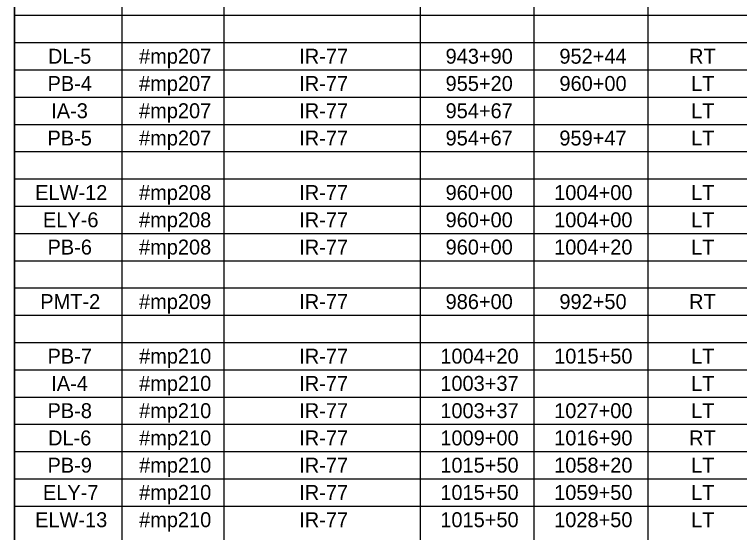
# Model space of a CAD drawing. Extents: x 91011267 to 91022583, y 37007614 to 37014266.
# Drawn here: x 91011277.4 to 91011642.6, y 37008138.9 to 37008399.9 of the extents above; entities that cross this region are included whole.
import ezdxf

# ---------------------------------------------------------------- set-up
doc = ezdxf.new("R2010")
doc.units = 0
doc.layers.add('SC_Scratch2', color=7, linetype='Continuous')
doc.layers.add('SH_Data', color=7, linetype='Continuous')

msp = doc.modelspace()

# ---------------------------------------------------------------- linework, layer by layer
at = {"layer": 'SC_Scratch2'}
msp.add_lwpolyline([(91011277.35, 37008663.81), (91012802.35, 37008663.81), (91012802.35, 37007613.81), (91011277.35, 37007613.81)], close=True, dxfattribs=at)
at = {"layer": 'SH_Data'}
for p, q in [((91011277.35, 37008481.94), (91011277.35, 37008372.04)), ((91011331.39, 37008481.94), (91011331.39, 37008372.04)), ((91011382.8, 37008481.94), (91011382.8, 37008372.04)), ((91011481.65, 37008481.94), (91011481.65, 37008372.04)), ((91011538.99, 37008481.94), (91011538.99, 37008372.04)), ((91011596.32, 37008481.94), (91011596.32, 37008372.04)), ((91011277.35, 37008399.51), (91011596.32, 37008399.51)), ((91011596.32, 37008399.51), (91011650.36, 37008399.51)), ((91011277.35, 37008385.77), (91011596.32, 37008385.77)), ((91011596.32, 37008385.77), (91011650.36, 37008385.77)), ((91011277.35, 37008372.04), (91011596.32, 37008372.04)), ((91011277.35, 37008372.04), (91011277.35, 37008358.3)), ((91011331.39, 37008372.04), (91011331.39, 37008358.3)), ((91011382.8, 37008372.04), (91011382.8, 37008358.3)), ((91011481.65, 37008372.04), (91011481.65, 37008358.3)), ((91011538.99, 37008372.04), (91011538.99, 37008358.3)), ((91011596.32, 37008372.04), (91011650.36, 37008372.04)), ((91011596.32, 37008372.04), (91011596.32, 37008358.3)), ((91011277.35, 37008358.3), (91011596.32, 37008358.3)), ((91011277.35, 37008358.3), (91011277.35, 37008330.82)), ((91011331.39, 37008358.3), (91011331.39, 37008330.82)), ((91011382.8, 37008358.3), (91011382.8, 37008330.82)), ((91011481.65, 37008358.3), (91011481.65, 37008330.82)), ((91011538.99, 37008358.3), (91011538.99, 37008330.82)), ((91011596.32, 37008358.3), (91011650.36, 37008358.3)), ((91011596.32, 37008358.3), (91011596.32, 37008330.82)), ((91011277.35, 37008344.56), (91011596.32, 37008344.56)), ((91011596.32, 37008344.56), (91011650.36, 37008344.56)), ((91011277.35, 37008330.82), (91011596.32, 37008330.82)), ((91011277.35, 37008330.82), (91011277.35, 37008317.08)), ((91011331.39, 37008330.82), (91011331.39, 37008317.08)), ((91011382.8, 37008330.82), (91011382.8, 37008317.08)), ((91011481.65, 37008330.82), (91011481.65, 37008317.08)), ((91011538.99, 37008330.82), (91011538.99, 37008317.08)), ((91011596.32, 37008330.82), (91011650.36, 37008330.82)), ((91011596.32, 37008330.82), (91011596.32, 37008317.08)), ((91011277.35, 37008317.08), (91011596.32, 37008317.08)), ((91011277.35, 37008317.08), (91011277.35, 37008303.34)), ((91011331.39, 37008317.08), (91011331.39, 37008303.34)), ((91011382.8, 37008317.08), (91011382.8, 37008303.34)), ((91011481.65, 37008317.08), (91011481.65, 37008303.34)), ((91011538.99, 37008317.08), (91011538.99, 37008303.34)), ((91011596.32, 37008317.08), (91011650.36, 37008317.08)), ((91011596.32, 37008317.08), (91011596.32, 37008303.34)), ((91011277.35, 37008303.34), (91011596.32, 37008303.34)), ((91011277.35, 37008303.34), (91011277.35, 37008289.61)), ((91011331.39, 37008303.34), (91011331.39, 37008289.61)), ((91011382.8, 37008303.34), (91011382.8, 37008289.61)), ((91011481.65, 37008303.34), (91011481.65, 37008289.61)), ((91011538.99, 37008303.34), (91011538.99, 37008289.61)), ((91011596.32, 37008303.34), (91011650.36, 37008303.34)), ((91011596.32, 37008303.34), (91011596.32, 37008289.61)), ((91011277.35, 37008289.61), (91011596.32, 37008289.61)), ((91011277.35, 37008289.61), (91011277.35, 37008083.53)), ((91011331.39, 37008289.61), (91011331.39, 37008083.53)), ((91011382.8, 37008289.61), (91011382.8, 37008083.53)), ((91011481.65, 37008289.61), (91011481.65, 37008083.53)), ((91011538.99, 37008289.61), (91011538.99, 37008083.53)), ((91011596.32, 37008289.61), (91011650.36, 37008289.61)), ((91011596.32, 37008289.61), (91011596.32, 37008083.53)), ((91011277.35, 37008275.87), (91011596.32, 37008275.87)), ((91011596.32, 37008275.87), (91011650.36, 37008275.87)), ((91011277.35, 37008262.13), (91011596.32, 37008262.13)), ((91011596.32, 37008262.13), (91011650.36, 37008262.13)), ((91011277.35, 37008248.39), (91011596.32, 37008248.39)), ((91011596.32, 37008248.39), (91011650.36, 37008248.39)), ((91011277.35, 37008234.65), (91011596.32, 37008234.65)), ((91011596.32, 37008234.65), (91011650.36, 37008234.65)), ((91011277.35, 37008220.91), (91011596.32, 37008220.91)), ((91011596.32, 37008220.91), (91011650.36, 37008220.91)), ((91011277.35, 37008207.18), (91011596.32, 37008207.18)), ((91011596.32, 37008207.18), (91011650.36, 37008207.18)), ((91011277.35, 37008193.44), (91011596.32, 37008193.44)), ((91011596.32, 37008193.44), (91011650.36, 37008193.44)), ((91011277.35, 37008179.7), (91011596.32, 37008179.7)), ((91011596.32, 37008179.7), (91011650.36, 37008179.7)), ((91011277.35, 37008165.96), (91011596.32, 37008165.96)), ((91011596.32, 37008165.96), (91011650.36, 37008165.96)), ((91011277.35, 37008152.22), (91011596.32, 37008152.22)), ((91011596.32, 37008152.22), (91011650.36, 37008152.22))]:
    msp.add_line(p, q, dxfattribs=at)

# ---------------------------------------------------------------- texts
for s, p in [('DL-5', (91011294.24, 37008375.14)), ('#mp207', (91011340.1, 37008375.14)), ('IR-77', (91011420.79, 37008375.14)), ('943+90', (91011494.52, 37008375.14)), ('952+44', (91011551.86, 37008375.14)), ('RT', (91011617.17, 37008375.14)), ('PB-4', (91011294.01, 37008361.4)), ('#mp207', (91011340.1, 37008361.4)), ('IR-77', (91011420.79, 37008361.4)), ('955+20', (91011494.52, 37008361.4)), ('960+00', (91011551.86, 37008361.4)), ('LT', (91011618.23, 37008361.4)), ('IA-3', (91011295.85, 37008347.67)), ('#mp207', (91011340.1, 37008347.67)), ('IR-77', (91011420.79, 37008347.67)), ('954+67', (91011494.51, 37008347.67)), ('LT', (91011618.23, 37008347.67)), ('PB-5', (91011293.97, 37008333.93)), ('#mp207', (91011340.1, 37008333.93)), ('IR-77', (91011420.79, 37008333.93)), ('954+67', (91011494.51, 37008333.93)), ('959+47', (91011551.84, 37008333.93)), ('LT', (91011618.23, 37008333.93)), ('ELW-12', (91011287.77, 37008306.45)), ('#mp208', (91011340.09, 37008306.45)), ('IR-77', (91011420.79, 37008306.45)), ('960+00', (91011494.52, 37008306.45)), ('1004+00', (91011549.21, 37008306.45)), ('LT', (91011618.23, 37008306.45)), ('ELY-6', (91011291.7, 37008292.71)), ('#mp208', (91011340.09, 37008292.71)), ('IR-77', (91011420.79, 37008292.71)), ('960+00', (91011494.52, 37008292.71)), ('1004+00', (91011549.21, 37008292.71)), ('LT', (91011618.23, 37008292.71)), ('PB-6', (91011293.99, 37008278.97)), ('#mp208', (91011340.09, 37008278.97)), ('IR-77', (91011420.79, 37008278.97)), ('960+00', (91011494.52, 37008278.97)), ('1004+20', (91011549.21, 37008278.97)), ('LT', (91011618.23, 37008278.97)), ('PMT-2', (91011290.33, 37008251.5)), ('#mp209', (91011340.09, 37008251.5)), ('IR-77', (91011420.79, 37008251.5)), ('986+00', (91011494.52, 37008251.5)), ('992+50', (91011551.86, 37008251.5)), ('RT', (91011617.17, 37008251.5)), ('PB-7', (91011293.99, 37008224.02)), ('#mp210', (91011340.11, 37008224.02)), ('IR-77', (91011420.79, 37008224.02)), ('1004+20', (91011491.87, 37008224.02)), ('1015+50', (91011549.21, 37008224.02)), ('LT', (91011618.23, 37008224.02)), ('IA-4', (91011295.87, 37008210.28)), ('#mp210', (91011340.11, 37008210.28)), ('IR-77', (91011420.79, 37008210.28)), ('1003+37', (91011491.86, 37008210.28)), ('LT', (91011618.23, 37008210.28)), ('PB-8', (91011293.99, 37008196.54)), ('#mp210', (91011340.11, 37008196.54)), ('IR-77', (91011420.79, 37008196.54)), ('1003+37', (91011491.86, 37008196.54)), ('1027+00', (91011549.21, 37008196.54)), ('LT', (91011618.23, 37008196.54)), ('DL-6', (91011294.26, 37008182.81)), ('#mp210', (91011340.11, 37008182.81)), ('IR-77', (91011420.79, 37008182.81)), ('1009+00', (91011491.87, 37008182.81)), ('1016+90', (91011549.21, 37008182.81)), ('RT', (91011617.17, 37008182.81)), ('PB-9', (91011293.99, 37008169.07)), ('#mp210', (91011340.11, 37008169.07)), ('IR-77', (91011420.79, 37008169.07)), ('1015+50', (91011491.87, 37008169.07)), ('1058+20', (91011549.21, 37008169.07)), ('LT', (91011618.23, 37008169.07)), ('ELY-7', (91011291.7, 37008155.33)), ('#mp210', (91011340.11, 37008155.33)), ('IR-77', (91011420.79, 37008155.33)), ('1015+50', (91011491.87, 37008155.33)), ('1059+50', (91011549.21, 37008155.33)), ('LT', (91011618.23, 37008155.33)), ('ELW-13', (91011287.73, 37008141.59)), ('#mp210', (91011340.11, 37008141.59)), ('IR-77', (91011420.79, 37008141.59)), ('1015+50', (91011491.87, 37008141.59)), ('1028+50', (91011549.21, 37008141.59)), ('LT', (91011618.23, 37008141.59))]:
    msp.add_text(s, height=7.523, dxfattribs=at).set_placement(p)

doc.saveas('drawing.dxf')
